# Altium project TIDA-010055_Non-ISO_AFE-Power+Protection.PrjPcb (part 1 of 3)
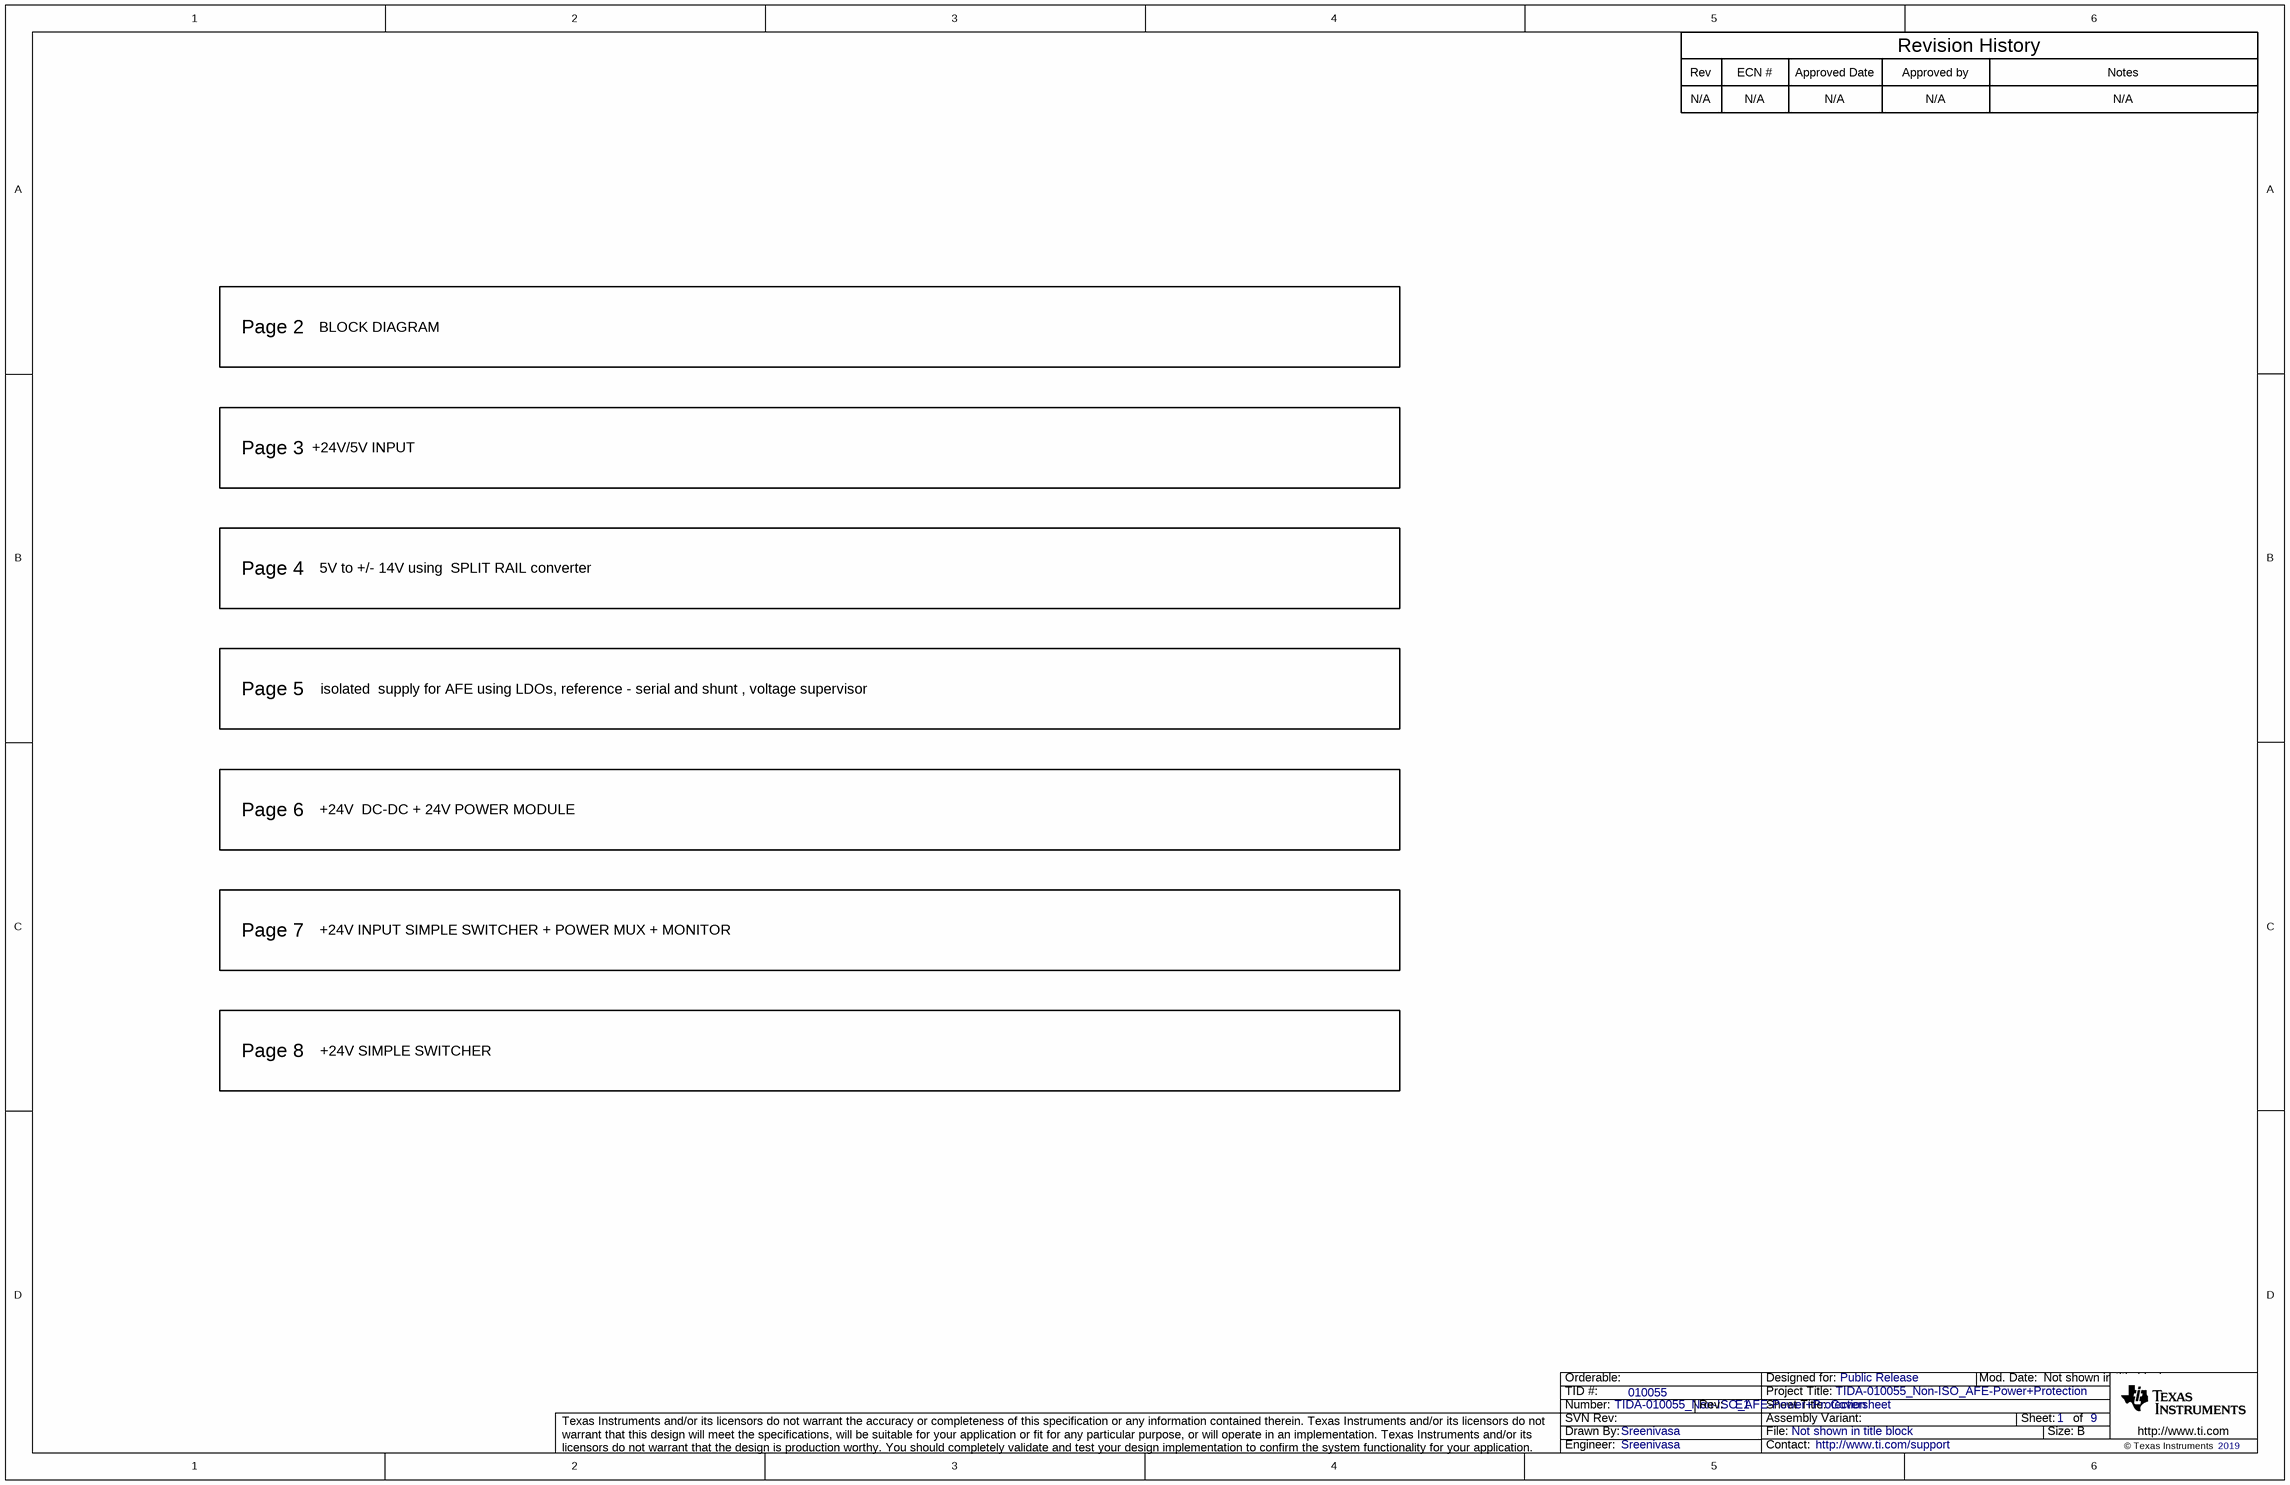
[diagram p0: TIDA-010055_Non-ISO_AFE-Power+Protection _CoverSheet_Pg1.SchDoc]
CopyrightYear: 2019; PCB_Layout: Avinash N; PCB_Rev: E1; PRJ_Customer: Public Release; PRJ_Engineer: Sreenivasa; PRJ_Number: TIDA-010055_Non-ISO_AFE-Power+Protection; PRJ_Title: TIDA-010055_Non-ISO_AFE-Power+Protection; SCH_Rev: E1; TechSupport: http://www.ti.com/support; TID: 010055
9 sheets, 399 parts. Net scope: flat (ports and power ports of the same name join across sheets).
Board file: TIDA-010055_Non-ISO_AFE-Power+Protection.PcbDoc
Sheets:
  TIDA-010055_Non-ISO_AFE-Power+Protection _CoverSheet_Pg1.SchDoc
  TIDA-010055_Non-ISO_AFE-Power+Protection _ Block Diagram_Pg2.SchDoc
  TIDA-010055_Non-ISO_AFE-Power+Protection _Pg3.SchDoc
  TIDA-010055_Non-ISO_AFE-Power+Protection _Pg4.SchDoc
  TIDA-010055_Non-ISO_AFE-Power+Protection _Pg5.SchDoc
  TIDA-010055_Non-ISO_AFE-Power+Protection _Pg6.SchDoc
  TIDA-010055_Non-ISO_AFE-Power+Protection _Pg7.SchDoc
  TIDA-010055_Non-ISO_AFE-Power+Protection _Pg8.SchDoc
  TIDA-010055_Non-ISO_AFE-Power+Protection _EVM_Hardware_Pg9.SchDoc

## Sheet TIDA-010055_Non-ISO_AFE-Power+Protection _CoverSheet_Pg1.SchDoc: Coversheet
size 431 x 279 mm; Date: Not shown in title block; ApprovedBy: Not shown in title block; CheckedBy: Not shown in title block; Author: Not shown in title block; CompanyName: Not shown in title block; DrawnBy: Sreenivasa; Engineer: Not shown in title block; Organization: Not shown in title block; Address1: Not shown in title block; Address2: Not shown in title block; Address3: Not shown in title block; Address4: Not shown in title block; DocumentNumber: 1; Revision: Use project parameter SCH_Rev; SheetNumber: 1; SheetTotal: 9; PageSetup: Record=PageOptions¦CenterHorizontal=True¦CenterVertical=True¦PrintScale=1.00¦XCorrection=1.00¦YCorrection=1.00¦PrintKind=0¦BorderSize=5000000¦LeftOffset=0¦BottomOffset=0¦Orientation=2¦PaperLength=1000¦PaperWidth=1000¦Scale=100¦PaperSource=15¦PrintQuality=600¦MediaType=1¦DitherType=10¦PaperKind=Letter¦PrintScaleMode=1

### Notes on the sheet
- Rev
- N/A
- ECN #
- Approved Date
- Approved by
- Revision History
- Notes
- Page 2
- BLOCK DIAGRAM
- Page 3
- +24V/5V INPUT
- Page 4
- 5V to +/- 14V using  SPLIT RAIL converter
- Page 5
- isolated  supply for AFE using LDOs, reference - serial and shunt , voltage supervisor
- Page 6
- +24V  DC-DC + 24V POWER MODULE
- Page 7
- +24V INPUT SIMPLE SWITCHER + POWER MUX + MONITOR
- Page 8
- +24V SIMPLE SWITCHER

## Sheet TIDA-010055_Non-ISO_AFE-Power+Protection _ Block Diagram_Pg2.SchDoc: Block Diagram
size 431 x 279 mm; Date: Not shown in title block; ApprovedBy: Not shown in title block; CheckedBy: Not shown in title block; Author: Not shown in title block; CompanyName: Not shown in title block; DrawnBy: Sreenivasa; Engineer: Sreenivasa; Organization: Not shown in title block; Address1: Not shown in title block; Address2: Not shown in title block; Address3: Not shown in title block; Address4: Not shown in title block; DocumentNumber: 1; Revision: Use project parameter SCH_Rev; SheetNumber: 2; SheetTotal: 9; PageSetup: Record=PageOptions¦CenterHorizontal=True¦CenterVertical=True¦PrintScale=1.00¦XCorrection=1.00¦YCorrection=1.00¦PrintKind=0¦BorderSize=5000000¦LeftOffset=0¦BottomOffset=0¦Orientation=2¦PaperLength=1000¦PaperWidth=1000¦Scale=100¦PaperSource=15¦PrintQuality=600¦MediaType=1¦DitherType=10¦PaperKind=Letter¦PrintScaleMode=1
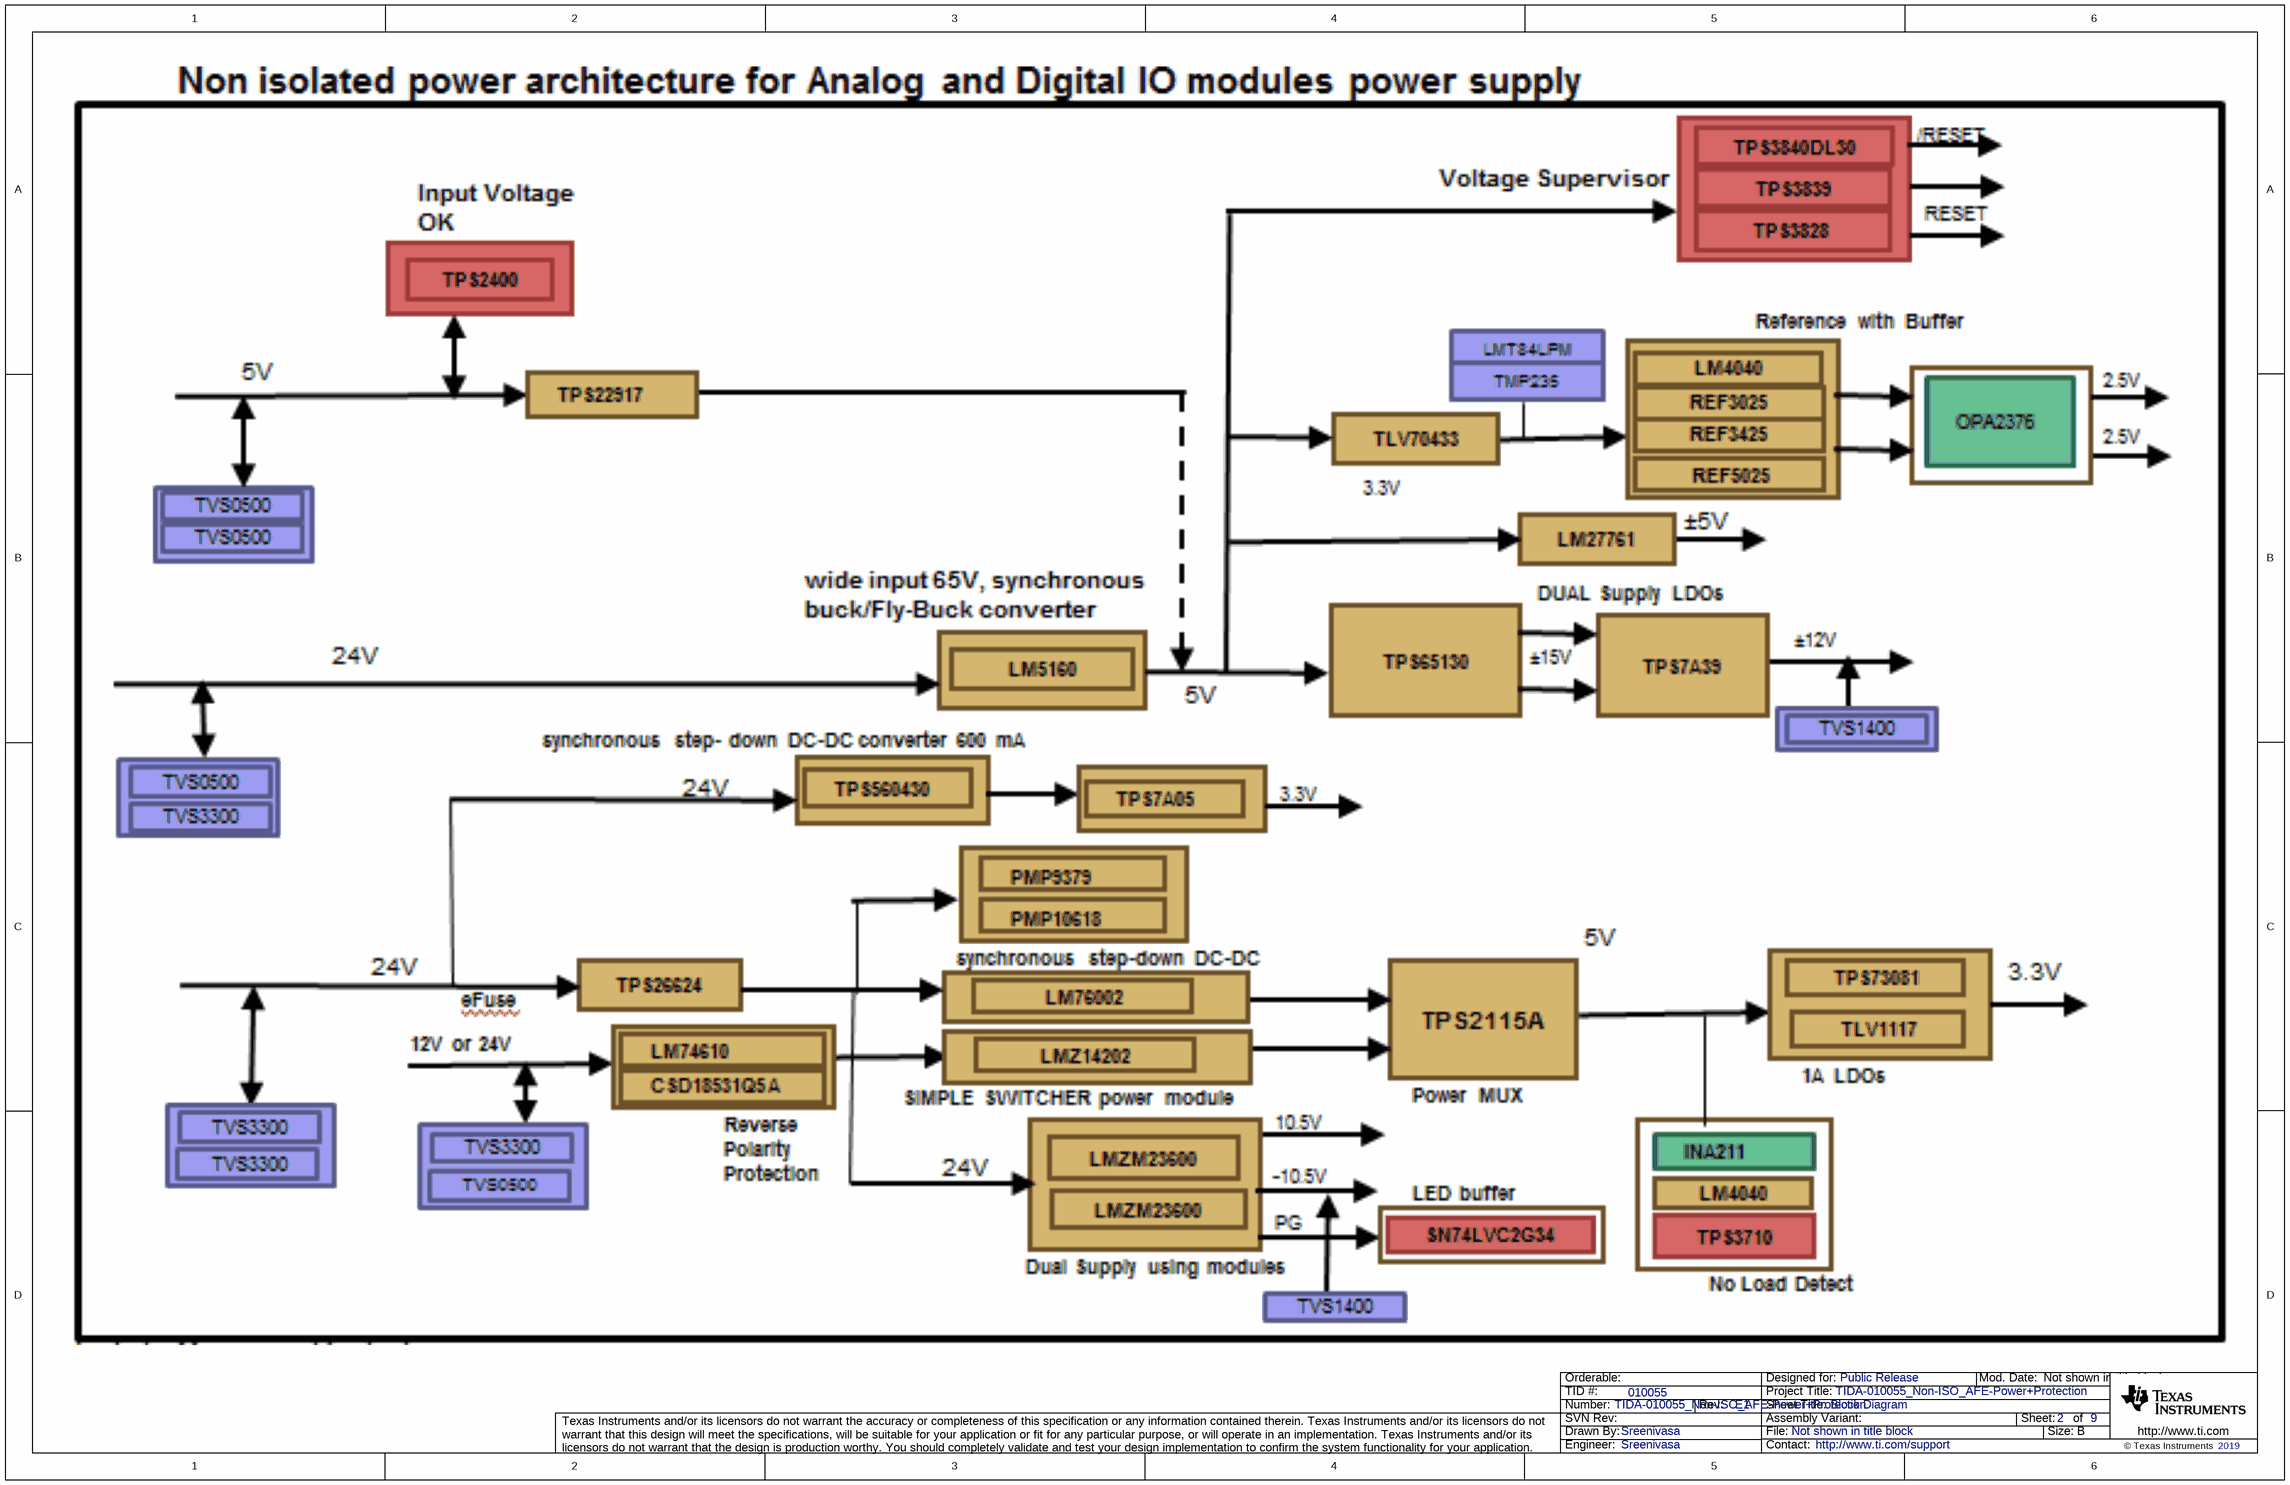
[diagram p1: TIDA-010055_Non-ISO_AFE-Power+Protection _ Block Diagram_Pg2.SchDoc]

## Sheet TIDA-010055_Non-ISO_AFE-Power+Protection _Pg3.SchDoc: +24V/5V INPUT ISOLATED DC-DC
size 431 x 279 mm; Date: Not shown in title block; ApprovedBy: Not shown in title block; CheckedBy: Not shown in title block; Author: Not shown in title block; CompanyName: Not shown in title block; DrawnBy: Sreenivasa; Engineer: Not shown in title block; Organization: Not shown in title block; Address1: Not shown in title block; Address2: Not shown in title block; Address3: Not shown in title block; Address4: Not shown in title block; DocumentNumber: 1; Revision: Use project parameter SCH_Rev; SheetNumber: 3; SheetTotal: 9; PageSetup: Record=PageOptions¦CenterHorizontal=True¦CenterVertical=True¦PrintScale=0.62¦XCorrection=1.00¦YCorrection=1.00¦PrintKind=0¦BorderSize=5000000¦LeftOffset=0¦BottomOffset=0¦Orientation=2¦PaperLength=1000¦PaperWidth=1000¦Scale=100¦PaperSource=15¦PrintQuality=600¦MediaType=1¦DitherType=10¦PrintScaleMode=1¦PaperKind=Letter
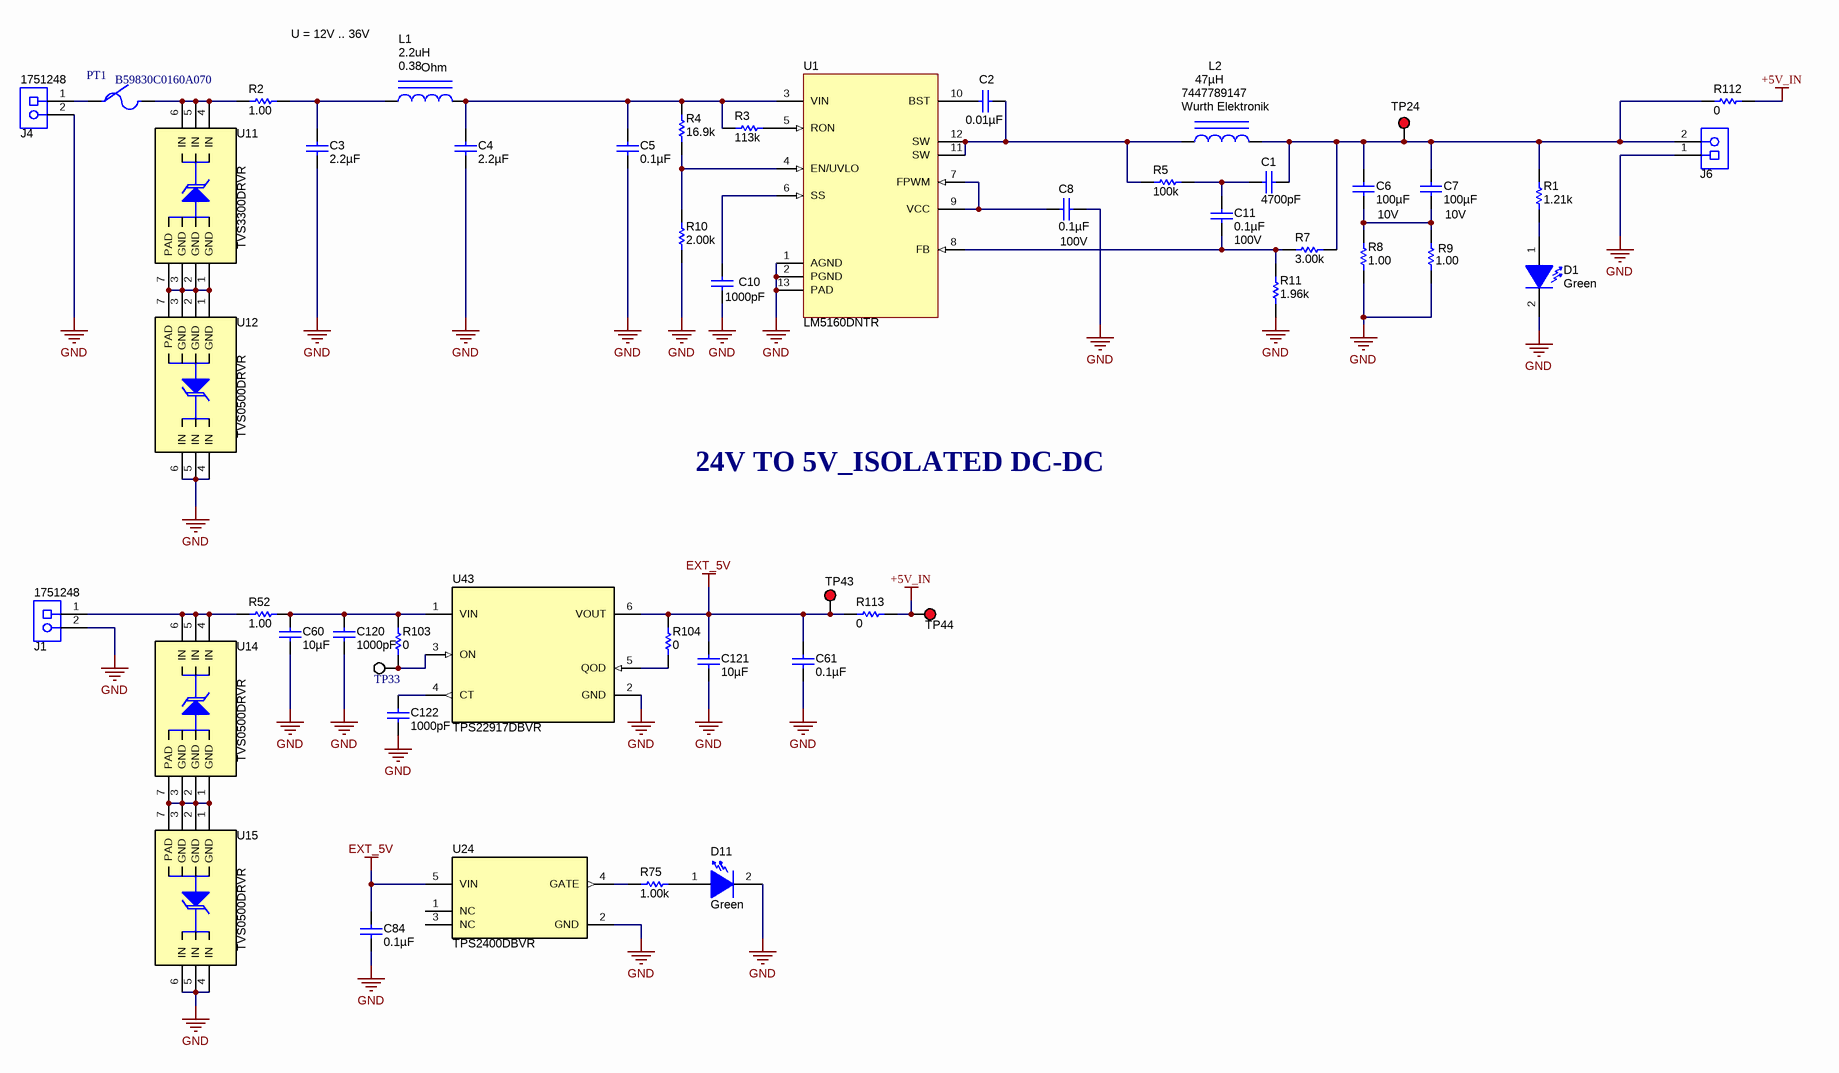
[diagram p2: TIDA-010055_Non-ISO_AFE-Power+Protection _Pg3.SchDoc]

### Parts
C1  ValueDisplayed: 4700pF  [0603]  (hidden comment: 06031C472KAT2A)
C2  ValueDisplayed: 0.01µF  [0603S]  (hidden comment: CGA3E2X7R1H103K080AA)
C3  ValueDisplayed: 2.2µF  [1206]  (hidden comment: UMK316B7225KL-T)
C4  ValueDisplayed: 2.2µF  [1206]  (hidden comment: UMK316B7225KL-T)
C5  ValueDisplayed: 0.1µF  [0603S]  (hidden comment: C0603X124K5RAC7867)
C6  ValueDisplayed: 100µF  Value2: 10V  [1210_280]  (hidden comment: C1210C107M8PACTU)
C7  ValueDisplayed: 100µF  Value2: 10V  [1210_280]  (hidden comment: C1210C107M8PACTU)
C8  ValueDisplayed: 0.1µF  Value2: 100V  [0805_HV]  (hidden comment: C0805C104K1RACTU)
C10  ValueDisplayed: 1000pF  [0603S]  (hidden comment: 885012206034)
C11  ValueDisplayed: 0.1µF  Value2: 100V  [0805_HV]  (hidden comment: C0805C104K1RACTU)
C60  ValueDisplayed: 10µF  [0805_HV]  (hidden comment: C2012X5R1E106K085AC)
C61  ValueDisplayed: 0.1µF  [0603]  (hidden comment: 06033D104KAT2A)
C84  ValueDisplayed: 0.1µF  [0603S]  (hidden comment: C0603X124K5RAC7867)
C120  ValueDisplayed: 1000pF  [0402]  (hidden comment: CGA2B2C0G1H102J050BA)
C121  ValueDisplayed: 10µF  [0805_HV]  (hidden comment: C2012X5R1E106K085AC)
C122  ValueDisplayed: 1000pF  [0402]  (hidden comment: CGA2B2C0G1H102J050BA)
D1  value Green  [LED_LTST-C190_G]  (hidden comment: LTST-C190KGKT)
D11  value Green  [LED_LTST-C190_G]  (hidden comment: LTST-C190KGKT)
J1  1751248  [CONN_1751248]
J4  1751248  [CONN_1751248]
J6  1751248  [CONN_1751248]  (value not drawn)
L1  2.2uH  DCR_ohm: 0.38  [0603L]
L2  7447789147  Manufacturer: Wurth Elektronik  ValueDisplayed: 47µH  [WE-PD-S]
PT1  B59830C0160A070  [POLYSWITCH_RXE135]
R1  ValueDisplayed: 1.21k  [0603S]  (hidden comment: CRCW06031K21FKEA)
R2  ValueDisplayed: 1.00  [0603S]  (hidden comment: CRCW06031R00FKEA)
R3  ValueDisplayed: 113k  [0603S]  (hidden comment: CRCW0603113KFKEA)
R4  ValueDisplayed: 16.9k  [0603S]  (hidden comment: CRCW060316K9FKEA)
R5  ValueDisplayed: 100k  [0603]  (hidden comment: RT0603FRE07100KL)
R7  ValueDisplayed: 3.00k  [0603]  (hidden comment: RC0603FR-073KL)
R8  ValueDisplayed: 1.00  [1206]  (hidden comment: RC1206FR-071RL)
R9  ValueDisplayed: 1.00  [1206]  (hidden comment: RC1206FR-071RL)
R10  ValueDisplayed: 2.00k  [0603S]  (hidden comment: CRCW06032K00FKEA)
R11  ValueDisplayed: 1.96k  [0603]  (hidden comment: RC0603FR-071K96L)
R52  ValueDisplayed: 1.00  [0603S]  (hidden comment: CRCW06031R00FKEA)
R75  ValueDisplayed: 1.00k  [0603]  (hidden comment: ERJ-3EKF1001V)
R103  ValueDisplayed: 0  [0603]  (hidden comment: ERJ-3GEY0R00V)
R104  ValueDisplayed: 0  [0603]  (hidden comment: ERJ-3GEY0R00V)
R112  ValueDisplayed: 0  [0805_HV]  (hidden comment: ERJ-6GEY0R00V)
R113  ValueDisplayed: 0  [0805_HV]  (hidden comment: ERJ-6GEY0R00V)
TP24  5000  [Keystone5000]  (value not drawn)
TP33  5002  [Keystone5002]  (value not drawn)
TP43  5000  [Keystone5000]  (value not drawn)
TP44  5000  [Keystone5000]  (value not drawn)
U1  LM5160DNTR  [DNT0012B]
U11  TVS3300DRVR  [DRV0006A]
U12  TVS0500DRVR  [DRV0006A]
U14  TVS0500DRVR  [DRV0006A]
U15  TVS0500DRVR  [DRV0006A]
U24  TPS2400DBVR  [DBV0005A_N]
U43  TPS22917DBVR  [DBV0006A_N]

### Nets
+5V_IN: R112.2 R113.2 TP44.1
EXT_5V: C61.1 C84.1 C121.1 R104.2 R113.1 TP43.1 U24.5(VIN) U43.6(VOUT)
GND: C3.2 C4.2 C5.2 C8.2 C10.2 C60.2 C61.2 C84.2 C120.2 C121.2 C122.2 D1.2(K) D11.2(K) J1.2 J4.2 J6.1 R8.1 R9.1 R10.1 R11.1 U1.1(AGND) U1.2(PGND) U1.13(PAD) U12.4(IN) U12.5(IN) U12.6(IN) U15.4(IN) U15.5(IN) U15.6(IN) U24.2(GND) U43.2(GND)
NetC1_1: C1.1 C6.1 C7.1 J6.2 L2.2 R1.1 R7.2 R112.1 TP24.1
NetC1_2: C1.2 C11.1 R5.2
NetC2_1: C2.1 U1.10(BST)
NetC2_2: C2.2 L2.1 R5.1 U1.11(SW) U1.12(SW)
NetC3_1: C3.1 L1.1 R2.1
NetC4_1: C4.1 C5.1 L1.2 R3.1 R4.2 U1.3(VIN)
NetC6_2: C6.2 C7.2 R8.2 R9.2
NetC8_1: C8.1 U1.7(FPWM) U1.9(VCC)
NetC10_1: C10.1 U1.6(SS)
NetC11_2: C11.2 R7.1 R11.2 U1.8(FB)
NetC60_1: C60.1 C120.1 R52.1 R103.2 U43.1(VIN)
NetC122_1: C122.1 U43.4(CT)
NetD1_1: D1.1(A) R1.2
NetD11_1: D11.1(A) R75.2
NetJ1_1: J1.1 R52.2 U14.4(IN) U14.5(IN) U14.6(IN)
NetJ4_1: J4.1 PT1.1
NetPT1_2: PT1.2 R2.2 U11.4(IN) U11.5(IN) U11.6(IN)
NetR3_2: R3.2 U1.5(RON)
NetR4_1: R4.1 R10.2 U1.4(EN/UVLO)
NetR75_1: R75.1 U24.4(GATE)
NetR103_1: R103.1 TP33.1 U43.3(ON)
NetR104_1: R104.1 U43.5(QOD)
NetU11_1: U11.1(GND) U11.2(GND) U11.3(GND) U11.7(PAD) U12.1(GND) U12.2(GND) U12.3(GND) U12.7(PAD)
NetU14_1: U14.1(GND) U14.2(GND) U14.3(GND) U14.7(PAD) U15.1(GND) U15.2(GND) U15.3(GND) U15.7(PAD)

Not connected (* = marked no-connect by the designer): U24 1(NC) 3(NC)

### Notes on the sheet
- U = 12V .. 36V
- (near L1) Ohm
- 24V TO 5V_ISOLATED DC-DC

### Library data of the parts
C1 = 06031C472KAT2A: CAP, CERM, 4700 pF, 100 V, +/- 10%, X7R, 0603; Manufacturer: AVX; Polarized: N; CompType: Capacitor; Value: 4700pF; U/M: EA; Cap_F: 0.0000000047; Tolerance_%: 10; ESR_ohm: 0.136; Value1: 0.136 ohm; VDC_V: 100; Value2: 100V; TaMin_C: -55; TaMax_C: 125
C2 = C0603C103J5RACTU: CAP, CERM, 0.01 µF, 50 V, +/- 5%, X7R, 0603; Manufacturer: TDK Corporation; Polarized: N; CompType: Capacitor; Value: 0.01uF; U/M: EA; Cap_F: 0.00000001; Tolerance_%: 5; Value1: Unknown; VDC_V: 50; Value2: 50V; TaMin_C: -55; TaMax_C: 125; Cap_Case: 0603; AEC Category: Q200
C3 C4 = UMK316B7225KL-T: CAP, CERM, 2.2 µF, 50 V,+/- 10%, X7R, 1206; Manufacturer: Taiyo Yuden; Polarized: N; CompType: Capacitor; Value: 2.2uF; U/M: EA; Cap_F: 0.0000022; Tolerance_%: 10; VDC_V: 50; Value2: 50V; TaMin_C: -55; TaMax_C: 125; AEC Category: Q200; SizeArea_mm2: 5.12; SizeAreaWB_mm2: 10.92; SizeX_mm: 3.2; SizeY_mm: 1.6; SizeZ_mm: 1.35
C5 C84 = C1608X7R1H104K: CAP, CERM, 0.12µF ±10% 50V Ceramic Capacitor X7R 0603; Manufacturer: KEMET; Polarized: N; Value: 0.1uF; U/M: EA; Cap_F: 0.0000001; Tolerance_%: 10; ESR_ohm: 0.017; Value1: 0.017 ohm; VDC_V: 50; TaMin_C: -55; TaMax_C: 125; Cap_Case: 0603; AEC Category: Q200
C6 C7 = C1210C107M8PACTU: CAP, CERM, 100 µF, 10 V, +/- 20%, X5R, 1210; Manufacturer: KEMET; Polarized: N; CompType: Capacitor; Value: 100uF; U/M: EA; Cap_F: 0.0001; Tolerance_%: 20; Value1: Unknown; VDC_V: 10; TaMin_C: -55; TaMax_C: 85; Cap_Case: 1210
C8 C11 = C0805C104K1RACTU: CAP, CERM, 0.1 µF, 100 V, +/- 10%, X7R, 0805; Manufacturer: Kemet; Polarized: N; CompType: Capacitor; Value: 0.1uF; U/M: EA; Cap_F: 0.0000001; Tolerance_%: 10; ESR_ohm: 0.064; Value1: 0.064 ohm; VDC_V: 100; IRMS_A: 1.64; TaMin_C: -55; TaMax_C: 125; Cap_Case: 0805
C10 = 885012206034: CAP, CERM, 1000 pF, 16 V, +/- 10%, X7R, 0603; Manufacturer: Wurth Elektronik; Polarized: N; CompType: Capacitor; Value: 1000pF; U/M: EA; Cap_F: 0.000000001; Tolerance_%: 10; Value1: Unknown; VDC_V: 16; Value2: 16V; TaMin_C: -55; TaMax_C: 125; Cap_Case: 0603; AEC Category: Q200
C60 C121 = GRM21BR61E106KA73L: CAP, CERM, 10 µF, 25 V, +/- 10%, X5R, 0805; Manufacturer: TDK Corporation; Polarized: N; CompType: Capacitor; Value: 10uF; U/M: EA; Cap_F: 0.00001; Tolerance_%: 10; Value1: Unknown; VDC_V: 25; Value2: 25V; TaMin_C: -55; TaMax_C: 85; Cap_Case: 0805; AEC Category: Q200
C61 = 06033D104KAT2A: CAP, CERM, 0.1 µF, 25 V,+/- 10%, X5R, 0603; Manufacturer: AVX; Polarized: N; CompType: Capacitor; Value: 0.1uF; U/M: EA; Cap_F: 0.0000001; Tolerance_%: 10; ESR_ohm: 0.048; Value1: 0.048 ohm; VDC_V: 25; Value2: 25V; IRMS_A: 0.53; TaMin_C: -55; TaMax_C: 85; AEC Category: Q200; SizeArea_mm2: 1.28; SizeAreaWB_mm2: 4.68; SizeX_mm: 1.6; SizeY_mm: 0.8; SizeZ_mm: 1; Green_Lifecycle: Active; Green_REACh: Passed
C120 C122 = CGA2B2C0G1H102J050BA: CAP, CERM, 1000 pF, 50 V,+/- 5%, C0G/NP0, AEC-Q200 Grade 1, 0402; Manufacturer: TDK; Polarized: N; CompType: Capacitor; Value: 1000pF; U/M: EA; Cap_F: 0.000000001; Tolerance_%: 5; VDC_V: 50; Value2: 50V; TaMin_C: -55; TaMax_C: 125; SizeArea_mm2: 0.5; SizeAreaWB_mm2: 3; SizeX_mm: 1; SizeZ_mm: 0.6; AEC Category: Q200; AEC Qualified: Y; Green_Lifecycle: Active; Green_REACh: Passed
D1 D11 = LTST-C190KGKT: LED, Green, SMD; Manufacturer: Lite-On; Type: AlInGaP; Vf_V: 2; Value2: 2V; Io_A: 0.03; Tjmax_C: 85; Value1: W; U/M: EA
J1 J4 J6 = 1751248: Conn Term Block, 2POS, 3.5mm, TH; Manufacturer: Phoenix Contact; CompType: Terminal Block; SymbolCreator: a0412235
L1 = LQM18PN2R2MFH: 2.2µH Shielded Multilayer Inductor 500mA 250mOhm 0603 (1608 Metric); PartNumber: MLZ1608A2R2WT000; Manufacturer: TDK Corporation; Imax_A: 0.35; Value1: 0.38 ohm; Value2: 0.35A; Ind_H: 2.2E-6; Irms: 0.9A @ 40C rise; Isat: 0.35A @ 30% inductance drop; Material: Ferrite; AEC Category: Q200
L2 = 7447789147: Inductor, Shielded Drum Core, Ferrite, 47 µH, 0.85 A, 0.315 ohm, SMD; Ind_H: 47.0E-6; Value: 47uH; Imax_A: 0.85; Irms: 0.85A @ 40C rise; Isat: 1A @ 10% inductance drop; DCR_ohm: 0.315; Value2: 0.85A
PT1 = POLYSWITCH_RXE135: PTC THERMISTOR C 830-A 160-A 70; Manufacturer: Raychem; Manufacturer: EPCOS (TDK); Area: 93750
R1 = CRCW06031K21FKEA: RES, 1.21 k, 1%, 0.1 W, 0603; Manufacturer: Vishay-Dale; CompType: Resistor; Value: 1.21k; Res_ohm: 1210; Value_Code: 1k21; Tolerance_%: 1; Power_W: 0.1; Value2: 0.1W; VDC_V: 75; TempCo: 100 ppm/C; EIA_Code: E96; U/M: EA; AEC Category: Q200
R2 R52 = CRCW06031R00FKEA: RES, 1.00, 1%, 0.1 W, 0603; Manufacturer: Vishay-Dale; CompType: Resistor; Value: 1.00; Res_ohm: 1; Value_Code: 1R00; Power_W: 0.1; Value2: 0.1W; VDC_V: 75; TempCo: 100 ppm/C; EIA_Code: E96; U/M: EA; AEC Category: Q200
R3 = CRCW0603113KFKEA: RES, 113 k, 1%, 0.1 W, 0603; Manufacturer: Vishay-Dale; CompType: Resistor; Value: 113k; Res_ohm: 113000; Tolerance_%: 1; Power_W: 0.1; Value2: 0.1W; VDC_V: 75; TempCo: 100 ppm/C; EIA_Code: E96; U/M: EA; AEC Category: Q200
R4 = CRCW060316K9FKEA: RES, 16.9 k, 1%, 0.1 W, 0603; Manufacturer: Vishay-Dale; CompType: Resistor; Value: 16.9k; Res_ohm: 16900; Value_Code: 16k9; Tolerance_%: 1; Power_W: 0.1; Value2: 0.1W; VDC_V: 75; TempCo: 100 ppm/C; EIA_Code: E96; U/M: EA; AEC Category: Q200
R5 = CRCW0603100KFKEA: RES, 100 k, 1%, 0.1 W, 0603; Manufacturer: Yageo America; CompType: Resistor; Value: 100k; Res_ohm: 100000; Tolerance_%: 1; Power_W: 0.1; Value2: 0.1W; VDC_V: 75; TempCo: 100 ppm/C; SizeArea_mm2: 1.28; SizeX_mm: 1.6; SizeY_mm: 0.8; EIA_Code: E96; U/M: EA; AEC Category: Q200; Green_Lifecycle: Active; Green_REACh: Passed
R7 = RC0603FR-073KL: RES, 3.00 k, 1%, 0.1 W, 0603; Manufacturer: Yageo America; CompType: Resistor; Value: 3.00k; Res_ohm: 3000; Value_Code: 3k00; Tolerance_%: 1; Power_W: 0.1; Value2: 0.1W; VDC_V: 150; TempCo: 200 ppm/C; SizeArea_mm2: 1.28; SizeX_mm: 1.6; SizeY_mm: 0.8; U/M: EA; AEC Category: Q200; Green_Lifecycle: Active; Green_REACh: Passed
R8 R9 = CRCW12061R00FKEA: RES, 1.00, 1%, 0.25 W, 1206; Manufacturer: Yageo America; CompType: Resistor; Value: 1.00; Res_ohm: 1; Value_Code: 1R00; Power_W: 0.25; Value2: 0.25W; VDC_V: 200; TempCo: 100 ppm/C; SizeArea_mm2: 5.12; SizeX_mm: 3.2; SizeY_mm: 1.6; SizeZ_mm: 1.35; EIA_Code: E96; U/M: EA; AEC Category: Q200; Green_Lifecycle: Active; Green_REACh: Passed
R10 = CRCW06032K00FKEA: RES, 2.00 k, 1%, 0.1 W, 0603; Manufacturer: Vishay-Dale; CompType: Resistor; Value: 2.00k; Res_ohm: 2000; Value_Code: 2k00; Tolerance_%: 1; Power_W: 0.1; Value2: 0.1W; VDC_V: 75; TempCo: 100 ppm/C; EIA_Code: E96; U/M: EA; AEC Category: Q200
R11 = RC0603FR-071K96L: RES, 1.96 k, 1%, 0.1 W, 0603; Manufacturer: Yageo America; CompType: Resistor; Value: 1.96k; Res_ohm: 1960; Value_Code: 1k96; Tolerance_%: 1; Power_W: 0.1; Value2: 0.1W; VDC_V: 150; TempCo: 200 ppm/C; SizeArea_mm2: 1.28; SizeX_mm: 1.6; SizeY_mm: 0.8; EIA_Code: E96; U/M: EA; AEC Category: Q200
R75 = ERJ-3EKF1001V: RES, 1.00 k, 1%, 0.1 W, AEC-Q200 Grade 0, 0603; Manufacturer: Panasonic; CompType: Resistor; Value: 1.00k; Res_ohm: 1000; Value_Code: 1k00; Tolerance_%: 1; Power_W: 0.1; Value2: 0.1W; VDC_V: 75; TempCo: 100 ppm/C; SizeArea_mm2: 1.28; SizeX_mm: 1.6; SizeY_mm: 0.8; EIA_Code: E96; U/M: EA; AEC Category: Q200; AEC Qualified: Y; AEC Grade: 0; Green_Lifecycle: Active; Green_REACh: Passed
R103 R104 = ERJ-3GEY0R00V: RES, 0, 5%, 0.1 W, 0603; Manufacturer: Panasonic; CompType: Resistor; Value: 0; Value_Code: 0000; Tolerance_%: 5; Power_W: 0.1; Value2: 0.1W; VDC_V: 50; TempCo: 600 ppm/C; SizeArea_mm2: 1.28; SizeX_mm: 1.6; SizeY_mm: 0.8; SizeZ_mm: 1; EIA_Code: E24; U/M: EA; AEC Category: Q200; Green_Lifecycle: Active; Green_REACh: Passed
R112 R113 = ERJ-6GEY0R00V: RES, 0, 5%, 0.125 W, 0805; Manufacturer: Panasonic; CompType: Resistor; Value: 0; Value_Code: 0000; Tolerance_%: 5; Power_W: 0.125; Value2: 0.125W; VDC_V: 150; TempCo: 600 ppm/C; SizeArea_mm2: 2.5; SizeX_mm: 2; SizeY_mm: 1.25; SizeZ_mm: 1.45; EIA_Code: E24; U/M: EA; AEC Category: Q200; Green_Lifecycle: Active; Green_REACh: Passed
TP24 = 5000: Test Point, Miniature, Red, TH; Manufacturer: Keystone; CompType: Test Point Loop; U/M: EA
TP33 = 5002: Test Point, Miniature, White, TH; Manufacturer: Keystone; CompType: Test Point Loop; ContactFinish: Silver; Green_Lifecycle: Active; Green_REACh: Passed
TP43 TP44 = 5000: Test Point, Miniature, Red, TH; Manufacturer: Keystone; CompType: Test Point Loop; ContactFinish: Silver
U1 = LM5160DNTR: Wide Input 65V, 1.5A Synchronous Step-Down DC-DC Converter, DNT0012B; Alternate PartNumber: LM5160DNTT; Manufacturer: Texas Instruments; SymbolCreator: a0411947; CompType: IC; U/M: EA
U11 = CMP-0013424-7: 33-V Precision Surge Protection Clamp, DRV0006A (WSON-6); Manufacturer: Texas Instruments; Alternate PartNumber: TVS3300DRVT; SizeX_mm: 2; CompType: IC; SizeZ_mm: 0.8; SizeArea_mm2: 4; SizeAreaWB_mm2: 9; U/M: EA
U12 U14 U15 = CMP-0077837-1: 5-V Precision Surge Protection Clamp, DRV0006A (WSON-6); Alternate Manufacturer: Texas Instruments; SizeAreaWB_mm2: 9.0; SizeZ_mm: 0.8; SizeX_mm: 2.0; SizeArea_mm2: 4.0; CompType: IC; AEC Qualified: N; AEC Category: Q200
U24 = CMP-0067322-1: Overvoltage/Undervoltage Protection IC in SOT-23-5, DBV0005A (SOT-23-5); Alternate PartNumber: TPS2400DBVT; Alternate Manufacturer: Texas Instruments; Green_Lifecycle: Active; SizeAreaWB_mm2: 14.82; Green_REACh: Passed; U/M: EA; SizeZ_mm: 1.45; SizeX_mm: 2.8; SizeY_mm: 2.9; SizeArea_mm2: 8.12
U43 = CMP-0077265-1: 5.5-V, 2-A, 80 mohm Low Leakage Load Switch with RCB and Programmable Rise Time, DBV0006A (SOT-23-6); Alternate PartNumber: TPS22917DBVT; Alternate Manufacturer: Texas Instruments; SizeAreaWB_mm2: 14.82; SizeZ_mm: 1.45; SizeX_mm: 2.8; SizeY_mm: 2.9; SizeArea_mm2: 8.12; CompType: IC; AEC Qualified: N; AEC Category: Q200

## Sheet TIDA-010055_Non-ISO_AFE-Power+Protection _Pg4.SchDoc: +/- 14V SPLIT RAIL
size 431 x 279 mm; Date: Not shown in title block; ApprovedBy: Not shown in title block; CheckedBy: Not shown in title block; Author: Not shown in title block; CompanyName: Not shown in title block; DrawnBy: Sreenivasa; Engineer: Not shown in title block; Organization: Not shown in title block; Address1: Not shown in title block; Address2: Not shown in title block; Address3: Not shown in title block; Address4: Not shown in title block; DocumentNumber: 1; Revision: Use project parameter SCH_Rev; SheetNumber: 4; SheetTotal: 9; PageSetup: Record=PageOptions¦CenterHorizontal=True¦CenterVertical=True¦PrintScale=0.62¦XCorrection=1.00¦YCorrection=1.00¦PrintKind=0¦BorderSize=5000000¦LeftOffset=0¦BottomOffset=0¦Orientation=2¦PaperLength=1000¦PaperWidth=1000¦Scale=100¦PaperSource=15¦PrintQuality=600¦MediaType=1¦DitherType=10¦PrintScaleMode=1¦PaperKind=Letter
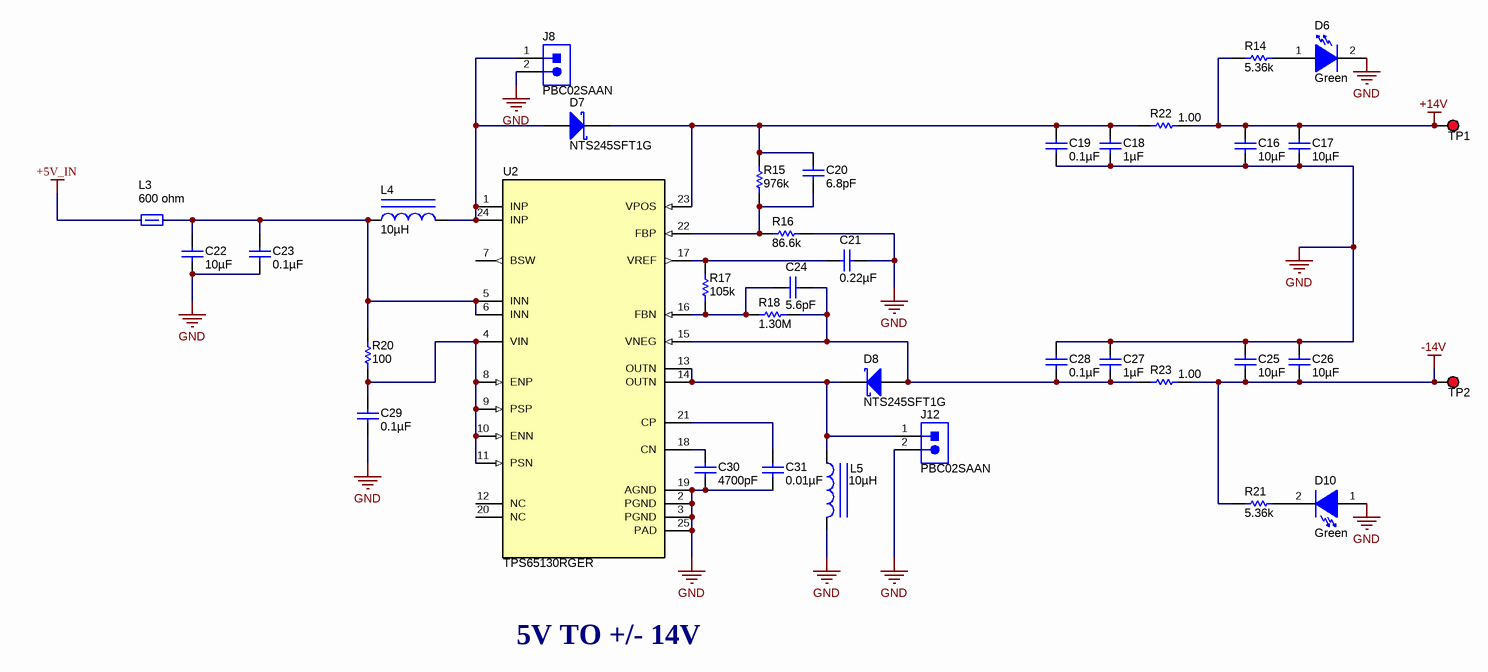
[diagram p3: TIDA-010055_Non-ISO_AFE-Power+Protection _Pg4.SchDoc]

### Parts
C16  ValueDisplayed: 10µF  [0805_HV]  (hidden comment: GRM21BC71E106KE11L)
C17  ValueDisplayed: 10µF  [0805_HV]  (hidden comment: GRM21BC71E106KE11L)
C18  ValueDisplayed: 1µF  [0603S]  (hidden comment: CGA3E1X7R1E105K080AC)
C19  ValueDisplayed: 0.1µF  [0603S]  (hidden comment: C0603X124K5RAC7867)
C20  ValueDisplayed: 6.8pF  [0603S]  (hidden comment: 06035A6R8CAT2A)
C21  ValueDisplayed: 0.22µF  [0603S]  (hidden comment: EMK107B7224KA-T)
C22  ValueDisplayed: 10µF  [0805_HV]  (hidden comment: GRM21BC71E106KE11L)
C23  ValueDisplayed: 0.1µF  [0603S]  (hidden comment: C0603X124K5RAC7867)
C24  ValueDisplayed: 5.6pF  [0603S]  (hidden comment: C0603C569K5GACTU)
C25  ValueDisplayed: 10µF  [0805_HV]  (hidden comment: GRM21BC71E106KE11L)
C26  ValueDisplayed: 10µF  [0805_HV]  (hidden comment: GRM21BC71E106KE11L)
C27  ValueDisplayed: 1µF  [0603S]  (hidden comment: CGA3E1X7R1E105K080AC)
C28  ValueDisplayed: 0.1µF  [0603S]  (hidden comment: C0603X124K5RAC7867)
C29  ValueDisplayed: 0.1µF  [0603S]  (hidden comment: C0603X124K5RAC7867)
C30  ValueDisplayed: 4700pF  [0603S]  (hidden comment: 885012206087)
C31  ValueDisplayed: 0.01µF  [0603S]  (hidden comment: 885012206040)
D6  value Green  [LED_LTST-C190_G]  (hidden comment: LTST-C190KGKT)
D7  NTS245SFT1G  [SOD-123FL]
D8  NTS245SFT1G  [SOD-123FL]
D10  value Green  [LED_LTST-C190_G]  (hidden comment: LTST-C190KGKT)
J8  PBC02SAAN  [Sullins_PBC02SAAN]
J12  PBC02SAAN  [Sullins_PBC02SAAN]
L3  value 600 ohm  [0603]  (hidden comment: BLM18KG601SN1D)
L4  ValueDisplayed: 10µH  [WE_LQS_252012]  (hidden comment: 74404024100)
L5  ValueDisplayed: 10µH  [WE_LQS_252012]  (hidden comment: 74404024100)
R14  ValueDisplayed: 5.36k  [0603S]  (hidden comment: CRCW06035K36FKEA)
R15  ValueDisplayed: 976k  [0603S]  (hidden comment: CRCW0603976KFKEA)
R16  ValueDisplayed: 86.6k  [0603S]  (hidden comment: CRCW060386K6FKEA)
R17  ValueDisplayed: 105k  [0603S]  (hidden comment: CRCW0603105KFKEA)
R18  ValueDisplayed: 1.30M  [0603S]  (hidden comment: CRCW06031M30FKEA)
R20  ValueDisplayed: 100  [0603S]  (hidden comment: CRCW0603100RFKEA)
R21  ValueDisplayed: 5.36k  [0603S]  (hidden comment: CRCW06035K36FKEA)
R22  ValueDisplayed: 1.00  [0603S]  (hidden comment: CRCW06031R00FKEA)
R23  ValueDisplayed: 1.00  [0603S]  (hidden comment: CRCW06031R00FKEA)
TP1  5000  [Keystone5000]  (value not drawn)
TP2  5000  [Keystone5000]  (value not drawn)
U2  TPS65130RGER  [RGE0024B]

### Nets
+5V_IN: L3.1
+14V: C16.1 C17.1 R14.1 R22.2 TP1.1
-14V: C25.2 C26.2 R21.2 R23.2 TP2.1
GND: C16.2 C17.2 C18.2 C19.2 C21.2 C22.2 C23.2 C25.1 C26.1 C27.1 C28.1 C29.2 C30.2 C31.2 D6.2(K) D10.1(A) J8.2 J12.2 L5.2 R16.1 U2.2(PGND) U2.3(PGND) U2.19(AGND) U2.25(PAD)
NetC18_1: C18.1 C19.1 C20.1 D7.1(K) R15.2 R22.1 U2.23(VPOS)
NetC20_2: C20.2 R15.1 R16.2 U2.22(FBP)
NetC21_1: C21.1 R17.2 U2.17(VREF)
NetC22_1: C22.1 C23.1 L3.2 L4.1 R20.2 U2.5(INN) U2.6(INN)
NetC24_1: C24.1 R17.1 R18.2 U2.16(FBN)
NetC24_2: C24.2 C27.2 C28.2 D8.2(A) R18.1 R23.1 U2.15(VNEG)
NetC29_1: C29.1 R20.1 U2.4(VIN) U2.8(ENP) U2.9(PSP) U2.10(ENN) U2.11(PSN)
NetC30_1: C30.1 U2.18(CN)
NetC31_1: C31.1 U2.21(CP)
NetD6_1: D6.1(A) R14.2
NetD7_2: D7.2(A) J8.1 L4.2 U2.1(INP) U2.24(INP)
NetD8_1: D8.1(K) J12.1 L5.1 U2.13(OUTN) U2.14(OUTN)
NetD10_2: D10.2(K) R21.1

Not connected (* = marked no-connect by the designer): U2 7(BSW) 12(NC) 20(NC)

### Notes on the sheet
- 5V TO +/- 14V

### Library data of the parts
C16 C17 C25 C26 = GRM21BC71E106KE11L: CAP, CERM, 10 µF, 25 V, +/- 10%, X7S, 0805; Manufacturer: MuRata; Polarized: N; CompType: Capacitor; Value: 10uF; U/M: EA; Cap_F: 0.00001; Tolerance_%: 10; Value1: Unknown; VDC_V: 25; Value2: 25V; TaMin_C: -55; TaMax_C: 125; Cap_Case: 0805; AEC Category: Q200
C18 C27 = GRM188R71E105KA12D: CAP, CERM, 1 µF, 25 V, +/- 10%, X7R, 0603; Manufacturer: TDK Corporation; Polarized: N; CompType: Capacitor; Value: 1uF; U/M: EA; Cap_F: 0.000001; Tolerance_%: 10; Value1: Unknown; VDC_V: 25; Value2: 25V; TaMin_C: -55; TaMax_C: 125; Cap_Case: 0603; AEC Category: Q200
C19 C23 C28 C29 = C1608X7R1H104K: as C5 on sheet TIDA-010055_Non-ISO_AFE-Power+Protection _Pg3
C20 = 06035A6R8CAT2A: CAP, CERM, 6.8 pF, 50 V, +/- 4%, C0G/NP0, 0603; Manufacturer: AVX; Polarized: N; CompType: Capacitor; Value: 6.8pF; U/M: EA; Cap_F: 0.0000000000068; Tolerance_%: 4; ESR_ohm: 0.505; Value1: 0.505 ohm; VDC_V: 50; Value2: 50V; TaMin_C: -55; TaMax_C: 125; Cap_Case: 0603; AEC Category: Q200
C21 = GRM188R71C224KA01D: CAP, CERM, 0.22 µF, 16 V, +/- 10%, X7R, 0603; Manufacturer: Taiyo Yuden; Polarized: N; CompType: Capacitor; Value: 0.22uF; U/M: EA; Cap_F: 0.00000022; Tolerance_%: 10; Value1: Unknown; VDC_V: 16; Value2: 16V; TaMin_C: -55; TaMax_C: 125; Cap_Case: 0603; AEC Category: Q200
C22 = GRM21BC71E106KE11L: CAP, CERM, 10 µF, 25 V,+/- 10%, X7S, 0805; Manufacturer: MuRata; Polarized: N; CompType: Capacitor; Value: 10uF; U/M: EA; Cap_F: 0.00001; Tolerance_%: 10; VDC_V: 25; Value2: 25V; TaMin_C: -55; TaMax_C: 125; Cap_Case: 0805; AEC Category: Q200; SizeArea_mm2: 2.5; SizeAreaWB_mm2: 6.75; SizeX_mm: 2; SizeY_mm: 1.25; SizeZ_mm: 1.45
C24 = 06035A5R6CAT2A: CAP, CERM, 5.6 pF, 50 V, +/- 5%, C0G/NP0, 0603; Manufacturer: KEMET; Polarized: N; CompType: Capacitor; Value: 5.6pF; U/M: EA; Cap_F: 0.0000000000056; Tolerance_%: 5; ESR_ohm: 0.568; Value1: 0.568 ohm; VDC_V: 50; Value2: 50V; TaMin_C: -55; TaMax_C: 125; Cap_Case: 0603; AEC Category: Q200
C30 = 885012206087: CAP, CERM, 4700 pF, 50 V, +/- 10%, X7R, 0603; Manufacturer: Wurth Elektronik; Polarized: N; CompType: Capacitor; Value: 4700pF; U/M: EA; Cap_F: 0.0000000047; Tolerance_%: 10; Value1: Unknown; VDC_V: 50; Value2: 50V; TaMin_C: -55; TaMax_C: 125; Cap_Case: 0603; AEC Category: Q200
C31 = 885012206040: CAP, CERM, 0.01 µF, 16 V, +/- 10%, X7R, 0603; Manufacturer: Wurth Elektronik; Polarized: N; CompType: Capacitor; Value: 0.01uF; U/M: EA; Cap_F: 0.00000001; Tolerance_%: 10; Value1: Unknown; VDC_V: 16; Value2: 16V; TaMin_C: -55; TaMax_C: 125; Cap_Case: 0603; AEC Category: Q200
D6 D10 = LTST-C190KGKT: as D1 on sheet TIDA-010055_Non-ISO_AFE-Power+Protection _Pg3
D7 D8 = NTS245SFT1G: Diode, Schottky, 45 V, 2 A, AEC-Q101, SOD-123FL; Manufacturer: ON Semiconductor; U/M: EA; Vf_V: 0.63; Value: 45V; Value1: 2A; Value2: 0.63V; Io_A: 2; Vr_V: 45; TJmax_C: 150; AEC Category: Q101; AEC Qualified: Y
J8 J12 = PBC02SAAN: Header, 100mil, 2x1, Gold, TH; Manufacturer: Sullins Connector Solutions; SymbolCreator: a0412235; Pitch_mm: 2.54; Gender: Male; Shrouded: N; Row_Count: 1; Current_A: 3; Voltage_V: 1800; Cert_UL: Y; Green_Lifecycle: Active; Green_REACh: Passed
L3 = BLM18KG601SN1D: Ferrite Bead, 600 ohm @ 100 MHz, 1.3 A, 0603; Manufacturer: MuRata; Imax_A: 1.3; DCR_ohm: 0.15; Value1: 0.15 ohm; Value2: 1.3A; ZTyp@100MHz_Ohm: 600
L4 L5 = 74404024100: Inductor, Wirewound, Ferrite, 10 µH, 0.47 A, 0.435 ohm, SMD; Manufacturer: Wurth Elektronik; Value: 10uH; Ind_H: 10.0E-6; Imax_A: 0.47; Irms: 0.47A @ 40C rise; Isat: 0.85A @ 30% inductance drop; DCR_ohm: 0.435; Value2: 0.47A; AEC Category: Q200
R14 R21 = CRCW06035K36FKEA: RES, 5.36 k, 1%, 0.1 W, 0603; Manufacturer: Vishay-Dale; CompType: Resistor; Value: 5.36k; Res_ohm: 5360; Value_Code: 5k36; Tolerance_%: 1; Power_W: 0.1; Value2: 0.1W; VDC_V: 75; TempCo: 100 ppm/C; EIA_Code: E96; U/M: EA; AEC Category: Q200
R15 = CRCW0603976KFKEA: RES, 976 k, 1%, 0.1 W, 0603; Manufacturer: Vishay-Dale; CompType: Resistor; Value: 976k; Res_ohm: 976000; Tolerance_%: 1; Power_W: 0.1; Value2: 0.1W; VDC_V: 75; TempCo: 100 ppm/C; EIA_Code: E96; U/M: EA; AEC Category: Q200
R16 = CRCW060386K6FKEA: RES, 86.6 k, 1%, 0.1 W, 0603; Manufacturer: Vishay-Dale; CompType: Resistor; Value: 86.6k; Res_ohm: 86600; Value_Code: 86k6; Tolerance_%: 1; Power_W: 0.1; Value2: 0.1W; VDC_V: 75; TempCo: 100 ppm/C; EIA_Code: E96; U/M: EA; AEC Category: Q200
R17 = CRCW0603105KFKEA: RES, 105 k, 1%, 0.1 W, 0603; Manufacturer: Vishay-Dale; CompType: Resistor; Value: 105k; Res_ohm: 105000; Tolerance_%: 1; Power_W: 0.1; Value2: 0.1W; VDC_V: 75; TempCo: 100 ppm/C; EIA_Code: E96; U/M: EA; AEC Category: Q200
R18 = CRCW06031M30FKEA: RES, 1.30 M, 1%, 0.1 W, 0603; Manufacturer: Vishay-Dale; CompType: Resistor; Value: 1.30Meg; Res_ohm: 1300000; Value_Code: 1M30; Tolerance_%: 1; Power_W: 0.1; Value2: 0.1W; VDC_V: 75; TempCo: 100 ppm/C; EIA_Code: E96; U/M: EA; AEC Category: Q200
R20 = CRCW0603100RFKEA: RES, 100, 1%, 0.1 W, 0603; Manufacturer: Vishay-Dale; CompType: Resistor; Value: 100; Value_Code: 100R; Tolerance_%: 1; Power_W: 0.1; Value2: 0.1W; VDC_V: 75; TempCo: 100 ppm/C; EIA_Code: E96; U/M: EA; AEC Category: Q200
R22 R23 = CRCW06031R00FKEA: as R2 on sheet TIDA-010055_Non-ISO_AFE-Power+Protection _Pg3
TP1 TP2 = 5000: as TP43 on sheet TIDA-010055_Non-ISO_AFE-Power+Protection _Pg3
U2 = TPS65130RGER: Positive and Negative Output DC-DC Converter, RGE0024B; Alternate PartNumber: TPS65130RGET; Manufacturer: Texas Instruments; SymbolCreator: a0411947; CompType: IC; U/M: EA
